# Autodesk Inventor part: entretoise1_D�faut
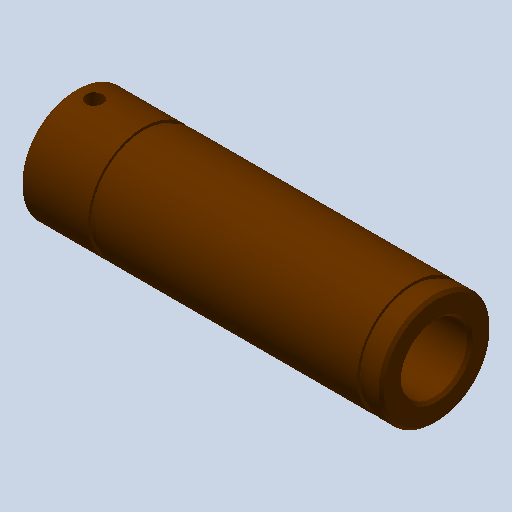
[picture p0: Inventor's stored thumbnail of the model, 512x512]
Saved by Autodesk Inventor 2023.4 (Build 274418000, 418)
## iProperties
Created: 2011-01
Part Number: entretoise1_D�faut
Document SubType Name: Modeling
Designer: eric
Density: 1 g/cm^3
Mass: 12.9074 g
Surface Area: 70.3958 cm^2
Volume: 12.9074 cm^3
Material: Générique
Appearance: 128,64,0_1
Author: eric
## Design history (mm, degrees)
feature "Base1"
node "Corps solides"
node "Corps surfaciques"
node "Solide1"
